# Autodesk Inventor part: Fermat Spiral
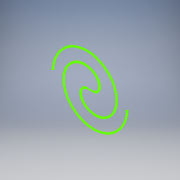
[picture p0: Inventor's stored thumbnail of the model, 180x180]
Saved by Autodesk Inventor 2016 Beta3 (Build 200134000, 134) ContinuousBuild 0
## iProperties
Created: 2008-02
Part Number: Fermat Spiral
Document SubType Name: Modeling
Designer: Autodesk, Inc.
Density: 1 g/cm^3
Material: Generic
Appearance: Default
Author: Autodesk, Inc.
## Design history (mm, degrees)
sketch "Sketch1"
  geometry: 301 further points
  constraints: 301 other
